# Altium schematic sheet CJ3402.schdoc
size 127 x 101 mm
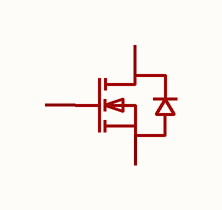
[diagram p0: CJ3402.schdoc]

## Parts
Q?  cj3402  [SOT-23_L2.9-W1.3-P1.90-LS2.4-BR]  (value not drawn)

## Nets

Not connected (* = marked no-connect by the designer): Q? 1(G) 2(S) 3(D)

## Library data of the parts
Q? = cj3402: 数量:1个N沟道;漏源电压(Vdss):30V;连续漏极电流(Id):4A;导通电阻(RDS(on)):55mΩ@10V;耗散功率(Pd):350mW;阈值电压(Vgs(th)):1.4V;; Manufacturer: CJ(江苏长电/长晶); AddInBom: yes; ModelId: c62791f0466c4ae2a892c056b845b0ca; ModelName: SOT-23-3P_L2.9-W1.3-H1.0-LS2.4-P0.95; ModelTransform: 98.64468,114.173,0,180,0,0,0.001,-0.002,0; Number: 1个N沟道; Drain to Source Voltage: 30V; Current - Continuous Drain(Id): 4A; Pd - Power Dissipation: 350mW; Gate Threshold Voltage (Vgs(th)): 1.4V; Gate Charge(Qg): 4.34nC; Input Capacitance(Ciss): 390pF; Reverse Transfer Capacitance (Crss@Vds): 41pF; Type: N沟道; Output Capacitance(Coss): 54.5pF; Vgs: ±12V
